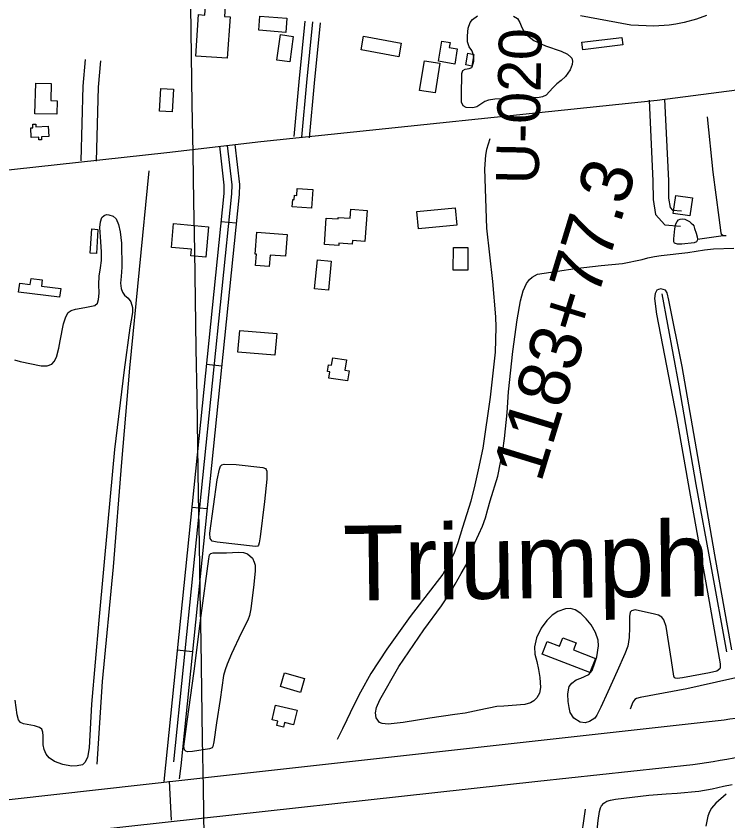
# Model space of a CAD drawing. Extents: x 3855477 to 3893699, y 299188 to 325115.
# Drawn here: x 3869933 to 3871314, y 308321 to 309881 of the extents above; entities that cross this region are included whole.
import ezdxf

# ---------------------------------------------------------------- set-up
doc = ezdxf.new("R2010")
doc.units = 0
for name, color, linetype in [('V-BLDG-OTLN', 7, 'Continuous'), ('V-GRID-MAJR', 7, 'Continuous'), ('V-LEVE-TOET', 7, 'Continuous'), ('V-RIVR-RANG-IDEN', 7, 'Continuous'), ('V-ROAD-CNTR', 7, 'Continuous'), ('V-SITE-VEGE', 7, 'Continuous'), ('V-SURV-IDEN', 7, 'Continuous'), ('V-TOPO-GNAM-IDEN', 7, 'Continuous'), ('V-TOPO-SHOR', 7, 'Continuous')]:
    doc.layers.add(name, color=color, linetype=linetype)

msp = doc.modelspace()

# ---------------------------------------------------------------- linework, layer by layer
at = {"layer": 'V-BLDG-OTLN'}
for points in [[(3870281.9, 309804.1), (3870287.3, 309884.3), (3870299.2, 309883.5), (3870302.6, 309934.8), (3870341.1, 309932.2), (3870337.7, 309880.8), (3870348.5, 309880.1), (3870343.1, 309800)], [(3870456.5, 309849.9), (3870403.9, 309854), (3870406, 309881.3), (3870458.6, 309877.2)], [(3870471, 309842.2), (3870464, 309792.6), (3870438.9, 309796.1), (3870445.9, 309845.8)], [(3870607.5, 309842.6), (3870680.3, 309829.1), (3870675.4, 309802.3), (3870602.5, 309815.9)], [(3871109.9, 309825.5), (3871032.4, 309816.2), (3871030.6, 309831), (3871108.1, 309840.3)], [(3870789.1, 309818.2), (3870784.2, 309788.6), (3870752.5, 309793.9), (3870759, 309832.9), (3870775, 309830.2), (3870773.4, 309820.7)], [(3870821.3, 309807.2), (3870817, 309784.6), (3870805.4, 309786.8), (3870809.7, 309809.4)], [(3870755.1, 309790), (3870746, 309732.8), (3870716.1, 309737.5), (3870725.2, 309794.8)], [(3869970, 309692.3), (3869971.6, 309751.4), (3870001.6, 309750.6), (3870000.7, 309717.8), (3870013, 309717.5), (3870012.3, 309691.2)], [(3870211.7, 309697.4), (3870214.2, 309741.4), (3870238.4, 309740), (3870235.9, 309696)], [(3869995.9, 309667.8), (3869996.8, 309648.2), (3869982.5, 309647.6), (3869982.8, 309641.7), (3869977.7, 309641.5), (3869977.5, 309647), (3869962.7, 309646.3), (3869961.8, 309664.8), (3869966.1, 309665), (3869965.8, 309671.9), (3869971.6, 309672.1), (3869971.8, 309666.7)], [(3870509.2, 309545.1), (3870506.4, 309508.8), (3870468.9, 309511.7), (3870470, 309526.1), (3870473, 309525.8), (3870473.6, 309534), (3870477.7, 309533.7), (3870478.8, 309547.5)], [(3871245.1, 309529.2), (3871240.3, 309494.1), (3871207.9, 309498.5), (3871212.7, 309533.6)], [(3870531.3, 309438.7), (3870534.9, 309489.8), (3870557.8, 309488.2), (3870558, 309491.2), (3870581.6, 309489.5), (3870582.9, 309507), (3870614.3, 309504.7), (3870610, 309444.7), (3870585.7, 309446.5), (3870585.2, 309439.1), (3870559.5, 309441), (3870559.2, 309436.7)], [(3870788.1, 309476), (3870713.7, 309468.8), (3870710.4, 309502.4), (3870784.9, 309509.6)], [(3870077, 309422), (3870080.2, 309468.8), (3870092.2, 309468), (3870089.1, 309421.2)], [(3870238.9, 309479.3), (3870306.8, 309473.1), (3870301.3, 309413.9), (3870272.6, 309416.5), (3870273.8, 309429.3), (3870234.7, 309432.9)], [(3870400.6, 309462.6), (3870459.4, 309457.8), (3870456, 309415.8), (3870426.4, 309418.2), (3870424.5, 309396), (3870397.6, 309398.2), (3870399.4, 309419.8), (3870397.1, 309420)], [(3870809.8, 309432.6), (3870809.3, 309388.7), (3870781.1, 309389), (3870781.7, 309432.9)], [(3870544.6, 309406.5), (3870539, 309350.1), (3870512.4, 309352.7), (3870518, 309409.1)], [(3870017.8, 309336.5), (3869938.3, 309346.5), (3869940.5, 309363.7), (3869961, 309361.1), (3869962.5, 309372.7), (3869984.1, 309369.9), (3869982.6, 309357.8), (3870019.9, 309353.1)], [(3870367.1, 309272.2), (3870439, 309265.8), (3870435.2, 309223.8), (3870363.4, 309230.2)], [(3870547.5, 309219.1), (3870574, 309215), (3870570.9, 309194.9), (3870579.2, 309193.6), (3870576.1, 309174), (3870539.9, 309179.6), (3870541.8, 309191.5), (3870537.6, 309192.1), (3870539.6, 309205.3), (3870545.2, 309204.4)], [(3871046.2, 308608.6), (3870953.6, 308644.3), (3870963.1, 308669), (3870987.3, 308659.6), (3870993.7, 308676.3), (3871019.6, 308666.3), (3871014.3, 308652.6), (3871056.8, 308636.2)], [(3870453.8, 308608.3), (3870492.7, 308597.1), (3870484.9, 308570.3), (3870446.1, 308581.5)], [(3870436.7, 308545.4), (3870478.3, 308535.5), (3870471.6, 308507.5), (3870454, 308511.7), (3870451.8, 308502.7), (3870438.9, 308505.8), (3870441, 308514.5), (3870430, 308517.1)]]:
    msp.add_lwpolyline(points, close=True, dxfattribs=at)
at = {"layer": 'V-GRID-MAJR'}
msp.add_spline([(3870354.6, 304789.8), (3870305.8, 307816.8), (3870207.9, 313876.8), (3870110.1, 319936.8), (3870061.1, 322969.9)], degree=3, dxfattribs=at)
at = {"layer": 'V-LEVE-TOET'}
msp.add_lwpolyline([(3871272.7, 309882.8), (3871252.8, 309875.8), (3871229.1, 309869), (3871213.2, 309865.8), (3871199.7, 309863.7), (3871170.5, 309862), (3871125.5, 309864), (3871080.3, 309872.1), (3871028.2, 309881.9)], dxfattribs=at)
at = {"layer": 'V-ROAD-CNTR'}
for p, q in [((3870360.5, 309479.8), (3870330.7, 309482.8)), ((3870332.2, 309202.9), (3870302.4, 309205.9)), ((3870303.9, 308926), (3870274.1, 308929)), ((3870275.6, 308649.1), (3870245.8, 308652.1))]:
    msp.add_line(p, q, dxfattribs=at)
for points in [[(3870407.9, 309638.5), (3871176.9, 309718.3), (3871625.5, 309776.4), (3872167.7, 309840.3), (3872558.4, 309887.1), (3873030.1, 309943.3), (3873155.3, 309958.3)], [(3870472.8, 309648.2), (3870482.3, 309754.2), (3870493.9, 309871.6)], [(3870487.8, 309646.8), (3870497.2, 309752.8), (3870508.8, 309870.2)], [(3870502.7, 309645.5), (3870512.2, 309751.4), (3870523.8, 309868.7)], [(3870059.5, 309600.9), (3870063.2, 309745.4), (3870068, 309797.4)], [(3870089.5, 309600.1), (3870093.2, 309743.6), (3870097.8, 309794.7)], [(3871161.2, 309718.8), (3871168.4, 309561.4), (3871168.9, 309526.1), (3871173.7, 309497), (3871191.9, 309476.6), (3871221.8, 309474.2)], [(3871191.2, 309720.2), (3871198.4, 309562.2), (3871198.8, 309528.7), (3871201.9, 309510.5), (3871206.3, 309505.5), (3871224.2, 309504.1)], [(3868552.9, 309441.2), (3868974.4, 309483.3), (3869758.1, 309565.8), (3870225.9, 309617), (3870407.9, 309638.5)], [(3870328.1, 309629.2), (3870336.5, 309553.7), (3870336.3, 309537.5), (3870219.7, 308397.4)], [(3870343, 309630.9), (3870351.6, 309554.4), (3870351.3, 309536.7), (3870238.7, 308435.3)], [(3870357.9, 309632.6), (3870366.6, 309555.1), (3870366.3, 309535.8), (3870253, 308427.8), (3870249.5, 308402.7)], [(3869428.7, 308307.8), (3870341.3, 308410), (3871306.7, 308516.8)], [(3869341.3, 308228.1), (3870087.3, 308303.6), (3870945.3, 308398.4), (3871246, 308430.1)], [(3870234.7, 308322.4), (3870230.9, 308398.2)]]:
    msp.add_lwpolyline(points, dxfattribs=at)
for points in [[(3871246, 308430.1), (3871456.8, 308465.5), (3871756, 308526.8), (3872125.9, 308626.4), (3872419.4, 308717.8), (3872694.2, 308826.9), (3872951.4, 308943.1), (3873197.2, 309062.5), (3873396.1, 309173.9), (3873603.2, 309301.5), (3873850.1, 309473.5), (3874076.9, 309643.6), (3874288.2, 309821.2), (3874524.7, 310044.2), (3874666.7, 310183.4)], [(3871306.7, 308516.8), (3871483.4, 308547.2), (3871799.6, 308615), (3872141.2, 308709.5), (3872363.6, 308783.1), (3872623.5, 308880.1), (3872867.9, 308988.6), (3873088.8, 309092.9), (3873264.9, 309189.6), (3873489.8, 309319.8), (3873684.7, 309452.1), (3873900.8, 309605.6), (3874069.5, 309735.8), (3874209.4, 309855.6), (3874334.7, 309968.6), (3874503.8, 310129.8)]]:
    msp.add_spline(points, degree=3, dxfattribs=at)
at = {"layer": 'V-SITE-VEGE'}
for points in [[(3870898.2, 309881.6), (3870905.8, 309876.9), (3870910.5, 309869), (3870914.5, 309859.3), (3870918.9, 309851.1), (3870926, 309842.9), (3870937.3, 309834.4), (3870959.9, 309824.1), (3870990.4, 309813.5), (3871002.6, 309807.5), (3871009.2, 309802), (3871010.9, 309799.9), (3871012.3, 309794.4), (3871011.9, 309787.4), (3871007.9, 309777.3), (3870998.8, 309764.3), (3870990.8, 309756.9), (3870982.4, 309750.1), (3870974.2, 309742.5), (3870968.1, 309735.2), (3870961.7, 309728.5), (3870954.6, 309724.8), (3870944.7, 309723), (3870936.7, 309723.5), (3870920.9, 309723), (3870862.1, 309720.6), (3870849.3, 309718.3), (3870842.4, 309715.9), (3870826.9, 309705.5), (3870819.2, 309703.4), (3870806.6, 309704), (3870800.4, 309707.7), (3870797.2, 309714.3), (3870797, 309734.3), (3870797.7, 309764.1), (3870797.6, 309769.9), (3870799.7, 309775.8), (3870804.2, 309778.4), (3870811.9, 309779.6), (3870817, 309781.7), (3870817.8, 309783.2), (3870821.1, 309793.9), (3870821.4, 309799.5), (3870820.7, 309806.1), (3870817, 309814.7), (3870812.3, 309821.7), (3870809, 309831.4), (3870809.2, 309843.4), (3870810.4, 309858), (3870813.9, 309869.2), (3870818.7, 309874.7), (3870828.3, 309881.7)], [(3870094.4, 309377.4), (3870097, 309393.5), (3870098.8, 309407.8), (3870099, 309424.5), (3870097.2, 309453.5), (3870095.6, 309471.5), (3870096.9, 309482.8), (3870099.6, 309491.1), (3870104.4, 309494.8), (3870108.9, 309496.5), (3870113.6, 309496.3), (3870121.4, 309493.4), (3870127.2, 309488.2), (3870131.9, 309477.5), (3870135, 309463.2), (3870137.6, 309441.4), (3870138.7, 309394.6), (3870136.9, 309376.9), (3870136.1, 309363.6), (3870137.4, 309353.4), (3870139.9, 309346.1), (3870144, 309340.6), (3870150.8, 309334.3), (3870156.1, 309327.2), (3870159.3, 309316.2), (3870158.9, 309306.9), (3870153.9, 309277), (3870142.9, 309195.7), (3870124.3, 309041.4), (3870111.1, 308900.6), (3870094.1, 308710.3), (3870079.7, 308547.2), (3870075.3, 308463), (3870071.9, 308444.3), (3870066.8, 308434.3), (3870062.3, 308430)], [(3871055.8, 308520.5), (3871045.7, 308514), (3871036.9, 308511.1), (3871027.3, 308512.4), (3871015, 308520.3), (3871008, 308531.1), (3871006, 308540.7), (3871004.1, 308552.5), (3871003.7, 308566.5), (3871004.6, 308575.2), (3871006.1, 308581.4), (3871011.5, 308588.3), (3871019.4, 308594.5), (3871028.6, 308598), (3871044.2, 308604.6), (3871050.7, 308612.4), (3871055.2, 308625.4), (3871059.4, 308639.4), (3871062.8, 308660.5), (3871062.3, 308671.5), (3871056.9, 308686.6), (3871048.6, 308701.3), (3871039, 308712.9), (3871028.5, 308723), (3871017.8, 308730.2), (3871008.7, 308732.6), (3870999.2, 308732.3), (3870984.3, 308727), (3870972.9, 308720), (3870962.5, 308709.6), (3870951.9, 308694.9), (3870942.5, 308676.3), (3870939, 308658.7), (3870939.2, 308644.3), (3870943.2, 308630.1), (3870946.4, 308614.9), (3870949, 308599.3), (3870950.6, 308580), (3870948.5, 308568.5), (3870943.1, 308559.7), (3870937.4, 308553.7), (3870931, 308550), (3870919.8, 308547), (3870879.4, 308543.8), (3870865.6, 308542.6), (3870831.4, 308535.8), (3870804.6, 308530.2), (3870784.6, 308527.2), (3870735.8, 308520.5), (3870684.2, 308511.9), (3870654.8, 308508.3), (3870643.6, 308509.7), (3870637.9, 308512), (3870631.7, 308520.6), (3870630.3, 308530.8), (3870632.4, 308540.9), (3870639, 308555.8), (3870675.6, 308620.3), (3870724, 308691.3), (3870758.2, 308737.8), (3870774, 308761.6), (3870785, 308779.8), (3870796.5, 308800.5), (3870807.5, 308819.4), (3870815.5, 308836.4), (3870819.1, 308852), (3870831.1, 308877.3), (3870837.9, 308892.5), (3870843.7, 308908.7), (3870848.3, 308925.4), (3870853, 308941.6), (3870867.4, 308989.3), (3870873.1, 309015.7), (3870877.2, 309039.4), (3870880.4, 309062.4), (3870885.9, 309112.4), (3870888.7, 309153.2), (3870896.8, 309231.5), (3870905.5, 309292.8), (3870911.5, 309329.2), (3870917, 309348.7), (3870923.3, 309362.9), (3870929.3, 309370.9), (3870934.5, 309375.5), (3870944.7, 309380.8), (3870983.3, 309387.2), (3871017.5, 309391.9), (3871068, 309398.1), (3871109.6, 309401.7), (3871147.7, 309409.7), (3871158.8, 309412.6), (3871171.7, 309415.1), (3871184.2, 309417.2), (3871236.5, 309423.3), (3871268.8, 309428.2), (3871285.9, 309430.5), (3871325.3, 309431.3)], [(3869930.1, 309214.7), (3869941.6, 309211.7), (3869982.1, 309203.2), (3869993.4, 309203.3), (3870002.5, 309206.3), (3870007.3, 309211.8), (3870011.8, 309220), (3870016.2, 309237.9), (3870019.2, 309252), (3870025.5, 309284.7), (3870029.7, 309298.2), (3870034.3, 309307), (3870040.3, 309310.6), (3870048.4, 309313.4), (3870066.8, 309316.6), (3870086.3, 309320.6), (3870091, 309325.2), (3870093.3, 309332), (3870094.4, 309344.2), (3870093.6, 309360.8), (3870094.4, 309377.4)], [(3871321.5, 308652.5), (3871312, 308706.1), (3871288.7, 308837.2), (3871258.4, 309012.6), (3871225.2, 309202), (3871199.1, 309330.7), (3871195.8, 309345.2), (3871193.1, 309349.9), (3871188.5, 309351.7), (3871183.8, 309352.4), (3871179.1, 309351.5), (3871176.3, 309349.8), (3871173.1, 309343.6), (3871171.6, 309334), (3871175.6, 309303.6), (3871214.2, 309103.2), (3871240.8, 308952.6), (3871277.7, 308746.3), (3871298.9, 308625.4), (3871299.1, 308619), (3871298, 308615.7), (3871292.5, 308611.7), (3871278.2, 308608.2), (3871225.7, 308598.3), (3871215.4, 308597.2), (3871212.5, 308597.6), (3871210.6, 308598.7), (3871208.9, 308601.7), (3871204.3, 308632.3), (3871193.9, 308698.1), (3871189.4, 308710.8), (3871185.6, 308716.1), (3871179.4, 308720), (3871171.8, 308722), (3871133.9, 308730.4), (3871127.1, 308728.5), (3871124.6, 308725.6), (3871122.8, 308717.3), (3871122.8, 308708), (3871123.3, 308695.9), (3871122.6, 308676.4), (3871119.8, 308660.1), (3871114.2, 308645.3), (3871099.4, 308611.5), (3871081.2, 308571.2), (3871067.4, 308541.3), (3871059.9, 308525.9), (3871055.8, 308520.5)], [(3870062.3, 308430), (3870052.2, 308427.6), (3870040.8, 308427), (3870024.3, 308430.2), (3870008, 308436.1), (3869997.6, 308443.5), (3869992, 308450.5), (3869987.8, 308459.8), (3869986.1, 308468.8), (3869985.9, 308477.2), (3869986.2, 308485.8), (3869985.5, 308493), (3869983.1, 308499.2), (3869979, 308502.4), (3869969, 308505.5), (3869947.7, 308509.4), (3869942.3, 308511.6), (3869937.9, 308517.2), (3869935.2, 308527), (3869931.5, 308555)], [(3871058.3, 308283.8), (3871062.6, 308321.8), (3871065.1, 308339.5), (3871067.1, 308346.4), (3871068.9, 308350.4), (3871073.5, 308355.6), (3871079.2, 308359.5), (3871086.5, 308361.4), (3871095.8, 308362.9), (3871160.5, 308371), (3871194, 308373.7), (3871215.2, 308375), (3871257.2, 308378.6), (3871283.3, 308383.2), (3871305.5, 308388.2), (3871322.2, 308391.5)]]:
    msp.add_lwpolyline(points, dxfattribs=at)
for points in [[(3870415.5, 308940.2), (3870406.7, 308871.6), (3870405, 308860.5), (3870403.8, 308856), (3870402.4, 308854), (3870397.8, 308852.9), (3870323.4, 308861.3), (3870314, 308863.6), (3870309.8, 308868.6), (3870309.4, 308878.9), (3870323.7, 308982.3), (3870327.9, 309002.8), (3870329.9, 309009.1), (3870332.4, 309011.7), (3870336.9, 309012.8), (3870360.1, 309012.1), (3870412.1, 309006.2), (3870416.9, 309004.4), (3870418.5, 309002.5), (3870419.9, 308999.4), (3870419.7, 308983.8)], [(3870335.9, 308603.1), (3870329.2, 308556.5), (3870321.9, 308511), (3870317.1, 308474.3), (3870315.3, 308465.2), (3870313.9, 308462.9), (3870308.7, 308460.6), (3870275.5, 308455.8), (3870266, 308455.1), (3870262.7, 308456.1), (3870259.9, 308458.6), (3870258.9, 308465.1), (3870265.2, 308513.8), (3870279.1, 308611.1), (3870292.4, 308719.5), (3870307.1, 308829.5), (3870308.6, 308836.7), (3870311.1, 308839.5), (3870315.7, 308841.1), (3870341.2, 308841.1), (3870364.6, 308842.4), (3870374.2, 308841.7), (3870382.5, 308838.7), (3870391.7, 308830.3), (3870395.3, 308822.9), (3870397, 308816.6), (3870396.9, 308805.9), (3870394.5, 308779.7), (3870388.4, 308732.1), (3870386, 308719.3), (3870382.6, 308710.3), (3870369.9, 308684.8), (3870351.3, 308644.8), (3870342.9, 308624.9), (3870338.8, 308613.9)]]:
    msp.add_lwpolyline(points, close=True, dxfattribs=at)
at = {"layer": 'V-TOPO-SHOR'}
for points in [[(3871273.4, 309686.3), (3871284.9, 309578.8), (3871296.2, 309490.8), (3871300.5, 309461.4), (3871301.1, 309459.2), (3871304.4, 309456.4), (3871307.1, 309456.3), (3871310.5, 309456.2)], [(3870851.9, 309643.8), (3870845.6, 309623.1), (3870843.5, 309612.1), (3870841.8, 309585.6), (3870845.5, 309470.6), (3870857.1, 309366.8), (3870863, 309298.2), (3870864.1, 309278.1), (3870862.4, 309230.1), (3870852.6, 309142.9), (3870838.5, 309043.9), (3870829.4, 309001.9), (3870823.1, 308972.8), (3870815.2, 308940.7), (3870799.4, 308889.7), (3870790.2, 308860.5), (3870782.1, 308838.9), (3870771.6, 308818.4), (3870760.9, 308799.2), (3870697.7, 308717.4), (3870652.5, 308654), (3870621.3, 308606.7), (3870601.5, 308570.6), (3870588.1, 308543.9), (3870574.6, 308517.2), (3870566.2, 308499.7), (3870555.9, 308478.6)], [(3870191.1, 309581.7), (3870172.3, 309390.3), (3870153.1, 309198.9), (3870137.8, 309016.3), (3870122, 308813.8), (3870100.3, 308591.4), (3870089.8, 308431)], [(3871249.3, 309469.8), (3871252.6, 309460.4), (3871254.4, 309453.4), (3871254.8, 309448.8), (3871254.4, 309446.4), (3871253.1, 309443.8), (3871248.3, 309441.8), (3871224.5, 309439.2), (3871215.9, 309439.3), (3871212.3, 309440.4), (3871210.4, 309441.4), (3871209, 309443.7), (3871208.9, 309449.6), (3871210.9, 309469.2), (3871213.2, 309478.5), (3871215.3, 309483.4), (3871218.1, 309486.5), (3871221.1, 309487.8), (3871226, 309488.4), (3871230.5, 309487.5), (3871235.3, 309485.4), (3871239.2, 309483.1), (3871242.7, 309480.2), (3871245.9, 309477.1), (3871247.7, 309474.6), (3871249.3, 309469.8)], [(3871327.8, 309456.8), (3871340.2, 309457), (3871354.4, 309456.9), (3871356.9, 309456.1), (3871359.7, 309454.3), (3871362, 309451.1), (3871363.8, 309443.3), (3871385.3, 309299.5), (3871410.7, 309135.2), (3871455.4, 308878.6), (3871491.4, 308650.2), (3871491.3, 308644.8), (3871490.5, 308641.8), (3871483.2, 308637.4), (3871355.5, 308604.3), (3871317.7, 308595.9), (3871234.2, 308577.4), (3871143.6, 308560.1), (3871136.9, 308558.3), (3871133.4, 308556.5), (3871129.6, 308551.4), (3871124.5, 308537.8)], [(3871254.8, 309448.8), (3871282, 309452.9), (3871304.4, 309456.4)], [(3871185.9, 309343.2), (3871218.5, 309164.6), (3871252, 308973.3), (3871280.7, 308815.7), (3871311.1, 308649.1)], [(3871310.3, 308373.2), (3871290.4, 308355.4), (3871282.1, 308345.5), (3871278.4, 308338.9), (3871274.9, 308330.5), (3871271.1, 308311.1)], [(3871036.8, 308343.5), (3871027.7, 308276.5), (3871023.5, 308241.7), (3871019.6, 308215.5), (3871014.9, 308197.2), (3870990.3, 308137.7), (3870944.2, 308041.1), (3870886.7, 307934.6), (3870842.9, 307862.3), (3870812.6, 307806.3), (3870789.7, 307768), (3870781.2, 307752.6), (3870773.9, 307736.1), (3870766.4, 307715.8), (3870758.3, 307691.9)]]:
    msp.add_lwpolyline(points, dxfattribs=at)

# ---------------------------------------------------------------- texts
at = {"layer": 'V-RIVR-RANG-IDEN'}
msp.add_text('U-020', height=83, rotation=88.7843, dxfattribs=at).set_placement((3870946.7, 309554.8))
at = {"layer": 'V-SURV-IDEN'}
msp.add_text('1183+77.3', height=100, rotation=72.994, dxfattribs=at).set_placement((3870951.3, 308975))
at = {"layer": 'V-TOPO-GNAM-IDEN'}
msp.add_text('Triumph', height=145, rotation=0.7186, dxfattribs=at).set_placement((3870568.4, 308748.2))

doc.saveas('drawing.dxf')
